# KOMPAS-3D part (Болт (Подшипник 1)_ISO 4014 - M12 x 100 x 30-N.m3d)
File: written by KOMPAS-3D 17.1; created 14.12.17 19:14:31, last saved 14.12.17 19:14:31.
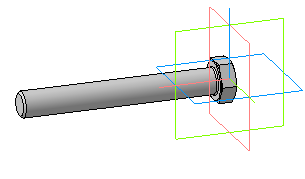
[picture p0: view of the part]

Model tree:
1. Операция без истории:1  (labels: Болт (Подшипник 1)_ISO 4014 - M12 x 100 x 30-N)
